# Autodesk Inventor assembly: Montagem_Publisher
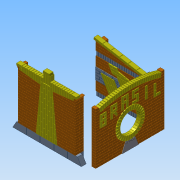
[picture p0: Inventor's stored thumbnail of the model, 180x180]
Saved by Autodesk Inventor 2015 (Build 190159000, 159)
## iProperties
Created: 2015-04
Part Number: Montagem_Publisher
Document SubType Name: Assembly
Designer: Paulo Kazuo Inoue
Author: Paulo Kazuo Inoue
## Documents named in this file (4)
- C:\Projetos_Kazuo\Workspace\WSI_Artes_Visuais\Grupo Kazuo\#20\Montagem_Publisher.iam
- C:\Projetos_Kazuo\Workspace\WSI_Artes_Visuais\Grupo Kazuo\#20\Modelo 1\Modulo 1.ipt
- C:\Projetos_Kazuo\Workspace\WSI_Artes_Visuais\Grupo Kazuo\#20\Modelo 2\Modulo 2.ipt
- C:\Projetos_Kazuo\Workspace\WSI_Artes_Visuais\Grupo Kazuo\#20\Modulo 3\Modulo 3.ipt
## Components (3 placed, 3 different names)
1. Modulo 1:1 — Flush:1, Angle:1
2. Modulo 2:1 — Flush:1, Flush:2, Angle:1, Angle:2
3. Modulo 3:1 — Flush:2, Angle:2
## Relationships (4: Flush 2, Angle 2)
- Flush:1: Modulo 1:1 ↔ Modulo 2:1
- Flush:2: Modulo 2:1 ↔ Modulo 3:1
- Angle:1: Modulo 1:1 ↔ Modulo 2:1
- Angle:2: Modulo 2:1 ↔ Modulo 3:1
